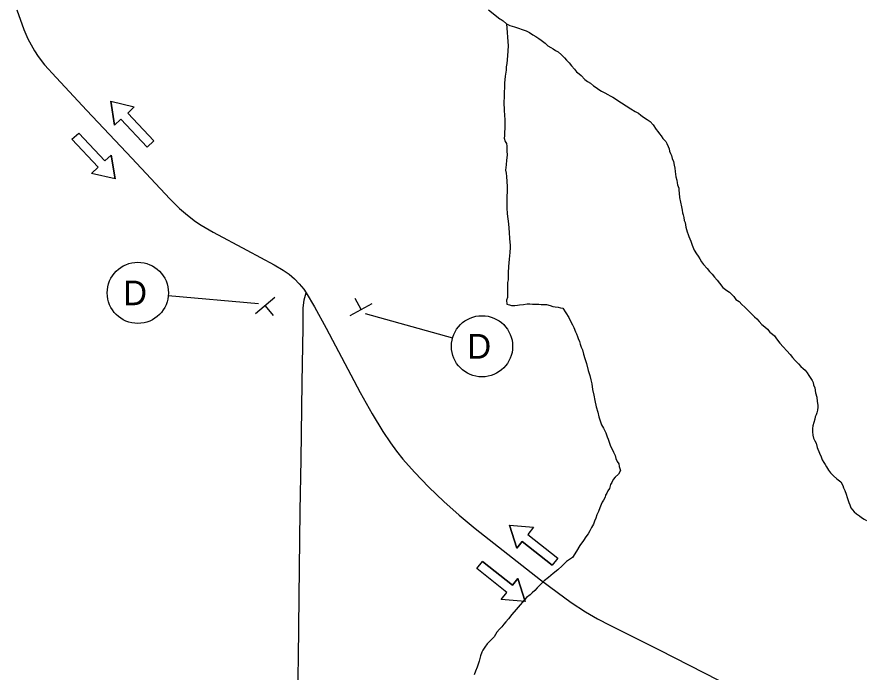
# Model space of a CAD drawing. Extents: x 1 to 1971, y -2 to 1107.
# Drawn here: x 1658.77 to 1664.12, y 1096.12 to 1100.26 of the extents above; entities that cross this region are included whole.
import ezdxf

# ---------------------------------------------------------------- set-up
doc = ezdxf.new("R2010")
doc.units = 0
for name, color, linetype in [('GM_X_Minor_River', 7, 'Continuous'), ('GM_X_State_Route', 7, 'Continuous'), ('GM_X_Township_Road', 7, 'Continuous'), ('SH_Text', 7, 'Continuous'), ('SN_P_Signs', 7, 'Continuous')]:
    doc.layers.add(name, color=color, linetype=linetype)

msp = doc.modelspace()

# ---------------------------------------------------------------- linework, layer by layer
at = {"layer": 'GM_X_Minor_River'}
for points in [[(1661.7482, 1100.3087), (1661.82, 1100.2515), (1661.828, 1100.2487), (1661.8414, 1100.2405), (1661.8626, 1100.2214), (1661.8839, 1100.2104), (1661.9134, 1100.202), (1661.9375, 1100.1937), (1661.9615, 1100.1853), (1661.9856, 1100.177), (1662.0069, 1100.166), (1662.0282, 1100.1523), (1662.0469, 1100.1413), (1662.0655, 1100.1277), (1662.0815, 1100.1168), (1662.1054, 1100.0977), (1662.124, 1100.0814), (1662.1427, 1100.0704), (1662.156, 1100.0622), (1662.172, 1100.0513), (1662.188, 1100.0431), (1662.2092, 1100.024), (1662.2278, 1100.005), (1662.2411, 1099.9915), (1662.257, 1099.9752), (1662.2728, 1099.9562), (1662.2914, 1099.9346), (1662.3046, 1099.9183), (1662.3205, 1099.9047), (1662.3338, 1099.8938), (1662.3577, 1099.8694), (1662.3736, 1099.8558), (1662.3923, 1099.8448), (1662.4109, 1099.8285), (1662.4295, 1099.8176), (1662.4455, 1099.8066), (1662.4615, 1099.7957), (1662.4828, 1099.7847), (1662.5015, 1099.7738), (1662.5175, 1099.7655), (1662.5335, 1099.7573), (1662.5895, 1099.7217), (1662.6188, 1099.7026), (1662.6481, 1099.6834), (1662.6747, 1099.667), (1662.6961, 1099.656), (1662.712, 1099.6424), (1662.728, 1099.6315), (1662.7519, 1099.6151), (1662.7706, 1099.6041), (1662.7891, 1099.5825), (1662.8076, 1099.5528), (1662.8181, 1099.5392), (1662.8287, 1099.5257), (1662.8393, 1099.5122), (1662.8498, 1099.496), (1662.8684, 1099.477), (1662.8763, 1099.4635), (1662.8841, 1099.4446), (1662.8893, 1099.4311), (1662.8918, 1099.4151), (1662.8997, 1099.4016), (1662.9049, 1099.3881), (1662.91, 1099.3693), (1662.9178, 1099.3504), (1662.9229, 1099.3263), (1662.9253, 1099.3075), (1662.9277, 1099.286), (1662.9327, 1099.2538), (1662.9378, 1099.2323), (1662.9403, 1099.2162), (1662.9428, 1099.2028), (1662.9506, 1099.1812), (1662.9504, 1099.1679), (1662.9529, 1099.1491), (1662.9552, 1099.1222), (1662.9679, 1099.0632), (1662.973, 1099.0417), (1662.9755, 1099.0255), (1662.978, 1099.0121), (1662.9832, 1098.996), (1662.9856, 1098.9772), (1662.9908, 1098.9637), (1662.9933, 1098.9503), (1662.9958, 1098.9342), (1663.0035, 1098.9047), (1663.0113, 1098.8885), (1663.0139, 1098.875), (1663.0269, 1098.8454), (1663.0347, 1098.8212), (1663.0477, 1098.7889), (1663.0635, 1098.7672), (1663.0741, 1098.751), (1663.0846, 1098.7348), (1663.0951, 1098.7159), (1663.1083, 1098.6997), (1663.1295, 1098.6726), (1663.1454, 1098.6537), (1663.1613, 1098.6374), (1663.1771, 1098.6184), (1663.193, 1098.5995)], [(1661.8626, 1100.2214), (1661.8716, 1100.082), (1661.8681, 1100.0178), (1661.8648, 1099.9696), (1661.8592, 1099.9483), (1661.8589, 1099.9268), (1661.8531, 1099.8894), (1661.8498, 1099.8466), (1661.8461, 1099.7609), (1661.8456, 1099.7234), (1661.8477, 1099.6752), (1661.8499, 1099.6403), (1661.8523, 1099.6162), (1661.852, 1099.5921), (1661.8516, 1099.5626), (1661.8485, 1099.5305), (1661.8483, 1099.5118), (1661.8481, 1099.4984), (1661.8532, 1099.4769), (1661.8611, 1099.4634), (1661.8636, 1099.4473), (1661.8634, 1099.4312), (1661.8632, 1099.4178), (1661.8656, 1099.391), (1661.8625, 1099.3589), (1661.8594, 1099.3295), (1661.8563, 1099.2947), (1661.8588, 1099.2759), (1661.8612, 1099.2545), (1661.8658, 1099.1928), (1661.8645, 1099.0964), (1661.8641, 1099.0562), (1661.8663, 1099.0187), (1661.8735, 1098.9569), (1661.8782, 1098.9006), (1661.8804, 1098.8631), (1661.8828, 1098.839), (1661.8852, 1098.8202), (1661.8851, 1098.8068), (1661.882, 1098.7747), (1661.8788, 1098.7319), (1661.8755, 1098.6864), (1661.8723, 1098.6463), (1661.872, 1098.6195), (1661.8717, 1098.6007), (1661.8689, 1098.5847), (1661.8687, 1098.5713), (1661.8683, 1098.5418), (1661.8677, 1098.4909), (1661.8621, 1098.4723), (1661.8645, 1098.4481), (1661.8805, 1098.4426), (1661.8939, 1098.4397), (1661.9154, 1098.4394), (1661.9315, 1098.4419), (1661.945, 1098.4444), (1661.9692, 1098.4467), (1661.9934, 1098.4491), (1662.0095, 1098.4489), (1662.0256, 1098.4487), (1662.039, 1098.4485), (1662.0659, 1098.4482), (1662.0819, 1098.4453), (1662.0954, 1098.4451), (1662.1142, 1098.4449), (1662.1383, 1098.4392), (1662.1543, 1098.4336), (1662.1704, 1098.4307), (1662.1891, 1098.4278), (1662.2025, 1098.4249), (1662.2186, 1098.4221), (1662.2555, 1098.3626), (1662.2685, 1098.3357), (1662.2791, 1098.3168), (1662.2869, 1098.3006), (1662.2973, 1098.2737), (1662.3052, 1098.2602), (1662.3104, 1098.2441), (1662.3156, 1098.2306), (1662.3234, 1098.2117), (1662.3286, 1098.1956), (1662.3337, 1098.1768), (1662.3415, 1098.1579), (1662.3492, 1098.1311), (1662.3569, 1098.1042), (1662.3673, 1098.0719), (1662.3775, 1098.0289), (1662.3878, 1097.9966), (1662.3955, 1097.9697), (1662.4006, 1097.9429), (1662.4055, 1097.908), (1662.4131, 1097.8731), (1662.4207, 1097.8381), (1662.4283, 1097.7979), (1662.4386, 1097.7656), (1662.4463, 1097.736), (1662.454, 1097.7091), (1662.4618, 1097.6849), (1662.4749, 1097.6633), (1662.4828, 1097.6471), (1662.4907, 1097.6336)], [(1663.193, 1098.5995), (1663.2089, 1098.5805), (1663.23, 1098.5535), (1663.254, 1098.5344), (1663.2726, 1098.5234), (1663.2859, 1098.5099), (1663.2991, 1098.4963), (1663.3123, 1098.4774), (1663.3336, 1098.4637), (1663.3495, 1098.4447), (1663.3681, 1098.4284), (1663.3893, 1098.4067), (1663.4106, 1098.3877), (1663.4291, 1098.3687), (1663.4451, 1098.3551), (1663.4583, 1098.3388), (1663.4769, 1098.3198), (1663.4954, 1098.3035), (1663.5114, 1098.2899), (1663.5273, 1098.271), (1663.5432, 1098.2574), (1663.5565, 1098.2465), (1663.5697, 1098.2275), (1663.5908, 1098.2005), (1663.6544, 1098.13), (1663.6703, 1098.1111), (1663.6861, 1098.0921), (1663.7073, 1098.0704), (1663.7233, 1098.0541), (1663.7365, 1098.0405), (1663.7498, 1098.0297), (1663.763, 1098.0134), (1663.7736, 1097.9972), (1663.7868, 1097.9783), (1663.7947, 1097.9648), (1663.7998, 1097.9513), (1663.8024, 1097.9379), (1663.8102, 1097.919), (1663.8151, 1097.8868), (1663.8229, 1097.8599), (1663.8252, 1097.8331), (1663.8303, 1097.8089), (1663.8301, 1097.7956), (1663.8272, 1097.7768), (1663.8243, 1097.7608), (1663.8188, 1097.7475), (1663.8132, 1097.7342), (1663.8104, 1097.7208), (1663.8047, 1097.6994), (1663.7991, 1097.6781), (1663.7962, 1097.6621), (1663.7959, 1097.6406), (1663.7983, 1097.6192), (1663.8035, 1097.6004), (1663.8113, 1097.5842), (1663.8192, 1097.568), (1663.8269, 1097.5411), (1663.8399, 1097.5061), (1663.8503, 1097.4819), (1663.8582, 1097.463), (1663.8687, 1097.4468), (1663.8766, 1097.4333), (1663.8845, 1097.4198), (1663.8976, 1097.3982), (1663.9108, 1097.382), (1663.9294, 1097.363), (1663.9506, 1097.344), (1663.9746, 1097.3249), (1663.9877, 1097.3006), (1663.9929, 1097.2871), (1664.0007, 1097.2683), (1664.0085, 1097.2468), (1664.0163, 1097.2252), (1664.0214, 1097.2064), (1664.0266, 1097.1929), (1664.0318, 1097.1795), (1664.0396, 1097.1606), (1664.0608, 1097.1336), (1664.0741, 1097.1227), (1664.0927, 1097.1091), (1664.106, 1097.0982), (1664.122, 1097.0872), (1664.138, 1097.079)], [(1662.4907, 1097.6336), (1662.4984, 1097.6094), (1662.5036, 1097.5933), (1662.5114, 1097.5744), (1662.5192, 1097.5502), (1662.527, 1097.5341), (1662.5375, 1097.5125), (1662.548, 1097.4909), (1662.5531, 1097.4721), (1662.5609, 1097.4532), (1662.5714, 1097.437), (1662.5739, 1097.4209), (1662.5817, 1097.3967), (1662.5706, 1097.3728), (1662.5489, 1097.3543), (1662.5353, 1097.3384), (1662.527, 1097.3198), (1662.5188, 1097.3065), (1662.5131, 1097.2824), (1662.5021, 1097.2665), (1662.4966, 1097.2532), (1662.4884, 1097.2399), (1662.4855, 1097.2265), (1662.4746, 1097.2079), (1662.4663, 1097.1947), (1662.4608, 1097.1813), (1662.4525, 1097.16), (1662.4441, 1097.136), (1662.4331, 1097.1147), (1662.4275, 1097.0934), (1662.4192, 1097.0747), (1662.4109, 1097.0561), (1662.3999, 1097.0348), (1662.3889, 1097.0135), (1662.3779, 1096.9949), (1662.3642, 1096.9763), (1662.3478, 1096.9525), (1662.3259, 1096.9206), (1662.304, 1096.8861), (1662.2793, 1096.8462), (1662.2414, 1096.8199), (1662.2142, 1096.7935), (1662.187, 1096.767), (1662.1572, 1096.7433), (1662.1273, 1096.7196), (1662.1002, 1096.6985), (1662.0757, 1096.6721), (1662.0567, 1096.6536), (1662.0404, 1096.6377), (1662.0241, 1096.6219), (1662.0105, 1096.6086), (1661.9888, 1096.5929), (1661.9234, 1096.516), (1661.8961, 1096.4843), (1661.8743, 1096.4577), (1661.8579, 1096.4392), (1661.8443, 1096.4233), (1661.8334, 1096.4074), (1661.8171, 1096.3915), (1661.8007, 1096.373), (1661.7842, 1096.3437), (1661.7598, 1096.3199), (1661.7407, 1096.2988), (1661.7243, 1096.2776), (1661.7133, 1096.259), (1661.7051, 1096.2457), (1661.6968, 1096.2243), (1661.6883, 1096.1896), (1661.6771, 1096.1523), (1661.666, 1096.1256), (1661.6577, 1096.1043)]]:
    msp.add_lwpolyline(points, dxfattribs=at)
at = {"layer": 'GM_X_State_Route'}
msp.add_lwpolyline([(1658.7669, 1100.3094), (1658.8112, 1100.1861), (1658.8364, 1100.1258), (1658.8558, 1100.0871), (1658.8777, 1100.0498), (1658.902, 1100.0139), (1658.9421, 1099.9626), (1659.015, 1099.8813), (1659.2096, 1099.6737), (1659.4941, 1099.3702), (1659.7329, 1099.1141), (1659.7949, 1099.0528), (1659.8441, 1099.01), (1659.8961, 1098.9708), (1659.9323, 1098.947), (1660.0079, 1098.9036), (1660.2199, 1098.7896), (1660.3938, 1098.6964), (1660.4506, 1098.6625), (1660.4869, 1098.6371), (1660.5209, 1098.6089), (1660.552, 1098.5772), (1660.5797, 1098.5427), (1660.5954, 1098.5194), (1660.6489, 1098.43), (1660.7226, 1098.2955), (1660.9376, 1097.8891), (1661.0117, 1097.7552), (1661.0794, 1097.643), (1661.1276, 1097.5702), (1661.1659, 1097.5174), (1661.2071, 1097.4667), (1661.2796, 1097.3852), (1661.3708, 1097.2909), (1661.4653, 1097.2001), (1661.5635, 1097.1133), (1661.6646, 1097.0297), (1662.0769, 1096.7044), (1662.1816, 1096.6253), (1662.2705, 1096.5618), (1662.3621, 1096.5026), (1662.4371, 1096.4581), (1662.5141, 1096.417), (1662.8274, 1096.2607), (1663.3928, 1095.972)], dxfattribs=at)
at = {"layer": 'GM_X_Township_Road'}
msp.add_lwpolyline([(1660.4916, 1092.3184), (1660.5024, 1093.5021), (1660.5078, 1093.787), (1660.5129, 1094.0937), (1660.5178, 1094.3786), (1660.5219, 1094.6414), (1660.5262, 1094.8383), (1660.5346, 1095.4947), (1660.5405, 1095.8685), (1660.5465, 1096.2115), (1660.5501, 1096.5938), (1660.5584, 1097.1408), (1660.5632, 1097.4654), (1660.5692, 1097.9522), (1660.5764, 1098.3001), (1660.5763, 1098.4243), (1660.58, 1098.4562), (1660.5825, 1098.4759), (1660.5954, 1098.5194)], dxfattribs=at)
msp.add_lwpolyline([(1660.4916, 1092.3184), (1660.5024, 1093.5021), (1660.5078, 1093.787), (1660.5129, 1094.0937), (1660.5178, 1094.3786), (1660.5219, 1094.6414), (1660.5262, 1094.8383), (1660.5346, 1095.4947), (1660.5405, 1095.8685), (1660.5465, 1096.2115), (1660.5501, 1096.5938), (1660.5584, 1097.1408), (1660.5632, 1097.4654), (1660.5692, 1097.9522), (1660.5764, 1098.3001), (1660.5763, 1098.4243), (1660.58, 1098.4562), (1660.5825, 1098.4759), (1660.5954, 1098.5194)], dxfattribs=at)
at = {"layer": 'SH_Text'}
for p, q in [((1659.3596, 1099.7311), (1659.5086, 1099.6958)), ((1659.3596, 1099.7311), (1659.3846, 1099.58)), ((1659.5086, 1099.6958), (1659.4669, 1099.6569)), ((1659.4669, 1099.6569), (1659.6321, 1099.4799)), ((1659.3846, 1099.58), (1659.4245, 1099.6173)), ((1659.4245, 1099.6173), (1659.5897, 1099.4404)), ((1659.1148, 1099.4908), (1659.1572, 1099.5304)), ((1659.28, 1099.3139), (1659.1148, 1099.4908)), ((1659.3224, 1099.3535), (1659.1572, 1099.5304)), ((1659.6321, 1099.4799), (1659.5897, 1099.4404)), ((1659.3623, 1099.3907), (1659.3224, 1099.3535)), ((1659.3873, 1099.2397), (1659.3623, 1099.3907)), ((1659.2383, 1099.275), (1659.28, 1099.3139)), ((1659.3873, 1099.2397), (1659.2383, 1099.275)), ((1660.2946, 1098.4509), (1659.7239, 1098.5003)), ((1660.9694, 1098.3893), (1661.5212, 1098.2355)), ((1661.8798, 1097.0493), (1662.0324, 1097.0366)), ((1661.8798, 1097.0493), (1661.927, 1096.9037)), ((1662.0324, 1097.0366), (1661.997, 1096.9919)), ((1661.997, 1096.9919), (1662.1867, 1096.8416)), ((1661.927, 1096.9037), (1661.9609, 1096.9465)), ((1661.9609, 1096.9465), (1662.1507, 1096.7962)), ((1661.6735, 1096.7752), (1661.7095, 1096.8207)), ((1661.8993, 1096.6704), (1661.7095, 1096.8207)), ((1662.1867, 1096.8416), (1662.1507, 1096.7962)), ((1661.8632, 1096.6249), (1661.6735, 1096.7752)), ((1661.9331, 1096.7131), (1661.8993, 1096.6704)), ((1661.9804, 1096.5675), (1661.9331, 1096.7131)), ((1661.8278, 1096.5802), (1661.8632, 1096.6249)), ((1661.9804, 1096.5675), (1661.8278, 1096.5802))]:
    msp.add_line(p, q, dxfattribs=at)
msp.add_lwpolyline([(1658.7669, 1100.3094), (1658.8112, 1100.1861), (1658.8364, 1100.1258), (1658.8558, 1100.0871), (1658.8777, 1100.0498), (1658.902, 1100.0139), (1658.9421, 1099.9626), (1659.015, 1099.8813), (1659.2096, 1099.6737), (1659.4941, 1099.3702), (1659.7329, 1099.1141), (1659.7949, 1099.0528), (1659.8441, 1099.01), (1659.8961, 1098.9708), (1659.9323, 1098.947), (1660.0079, 1098.9036), (1660.2199, 1098.7896), (1660.3938, 1098.6964), (1660.4506, 1098.6625), (1660.4869, 1098.6371), (1660.5209, 1098.6089), (1660.552, 1098.5772), (1660.5797, 1098.5427), (1660.5954, 1098.5194), (1660.6489, 1098.43), (1660.7226, 1098.2955), (1660.9376, 1097.8891), (1661.0117, 1097.7552), (1661.0794, 1097.643), (1661.1276, 1097.5702), (1661.1659, 1097.5174), (1661.2071, 1097.4667), (1661.2796, 1097.3852), (1661.3708, 1097.2909), (1661.4653, 1097.2001), (1661.5635, 1097.1133), (1661.6646, 1097.0297), (1662.0769, 1096.7044), (1662.1816, 1096.6253), (1662.2705, 1096.5618), (1662.3621, 1096.5026), (1662.4371, 1096.4581), (1662.5141, 1096.417), (1662.8274, 1096.2607), (1663.3928, 1095.972)], dxfattribs=at)
msp.add_lwpolyline([(1658.7669, 1100.3094), (1658.8112, 1100.1861), (1658.8364, 1100.1258), (1658.8558, 1100.0871), (1658.8777, 1100.0498), (1658.902, 1100.0139), (1658.9421, 1099.9626), (1659.015, 1099.8813), (1659.2096, 1099.6737), (1659.4941, 1099.3702), (1659.7329, 1099.1141), (1659.7949, 1099.0528), (1659.8441, 1099.01), (1659.8961, 1098.9708), (1659.9323, 1098.947), (1660.0079, 1098.9036), (1660.2199, 1098.7896), (1660.3938, 1098.6964), (1660.4506, 1098.6625), (1660.4869, 1098.6371), (1660.5209, 1098.6089), (1660.552, 1098.5772), (1660.5797, 1098.5427), (1660.5954, 1098.5194), (1660.6489, 1098.43), (1660.7226, 1098.2955), (1660.9376, 1097.8891), (1661.0117, 1097.7552), (1661.0794, 1097.643), (1661.1276, 1097.5702), (1661.1659, 1097.5174), (1661.2071, 1097.4667), (1661.2796, 1097.3852), (1661.3708, 1097.2909), (1661.4653, 1097.2001), (1661.5635, 1097.1133), (1661.6646, 1097.0297), (1662.0769, 1096.7044), (1662.1816, 1096.6253), (1662.2705, 1096.5618), (1662.3621, 1096.5026), (1662.4371, 1096.4581), (1662.5141, 1096.417), (1662.8274, 1096.2607), (1663.3928, 1095.972)], dxfattribs=at)
for points in [[(1659.5897, 1099.4404), (1659.4245, 1099.6173), (1659.3846, 1099.58), (1659.3596, 1099.7311), (1659.5086, 1099.6958), (1659.4669, 1099.6569), (1659.6321, 1099.48)], [(1659.1572, 1099.5304), (1659.3224, 1099.3535), (1659.3623, 1099.3907), (1659.3873, 1099.2397), (1659.2383, 1099.275), (1659.28, 1099.3139), (1659.1148, 1099.4908)], [(1662.1506, 1096.7962), (1661.9609, 1096.9465), (1661.927, 1096.9037), (1661.8798, 1097.0493), (1662.0324, 1097.0366), (1661.997, 1096.9919), (1662.1867, 1096.8416)], [(1661.7095, 1096.8207), (1661.8993, 1096.6704), (1661.9332, 1096.7131), (1661.9804, 1096.5675), (1661.8278, 1096.5802), (1661.8632, 1096.6249), (1661.6735, 1096.7752)]]:
    msp.add_lwpolyline(points, close=True, dxfattribs=at)
for centre in [(1659.5312, 1098.5192), (1661.7071, 1098.1814)]:
    msp.add_circle(centre, 0.1936, dxfattribs=at)
at = {"layer": 'SN_P_Signs'}
for p, q in [((1660.3965, 1098.4896), (1660.274, 1098.3866)), ((1660.9427, 1098.414), (1660.9043, 1098.4841)), ((1660.3352, 1098.4381), (1660.3868, 1098.3768)), ((1660.8725, 1098.3756), (1661.0129, 1098.4524))]:
    msp.add_line(p, q, dxfattribs=at)

# ---------------------------------------------------------------- texts
at = {"layer": 'SH_Text'}
for p in [(1659.4382, 1098.4412), (1661.6141, 1098.1034)]:
    msp.add_text('D', height=0.156, dxfattribs=at).set_placement(p)

doc.saveas('drawing.dxf')
